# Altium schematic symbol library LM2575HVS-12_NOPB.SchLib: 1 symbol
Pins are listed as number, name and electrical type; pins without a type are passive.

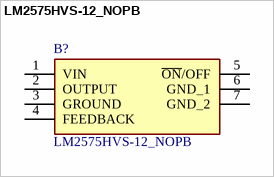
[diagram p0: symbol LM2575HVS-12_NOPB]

## LM2575HVS-12_NOPB
designator B?
Texas Instruments, LM2575HVS-12/NOPB Step-Down Switching Regulator 1A, 1.23  57 V, 5-Pin TO-263; Geometry.Height: 4.65mm
footprint LM2575HVS12NOPB
pins: 1 VIN, 2 OUTPUT, 3 GROUND, 4 FEEDBACK, 5 ~{ON}/OFF, 6 GND_1, 7 GND_2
